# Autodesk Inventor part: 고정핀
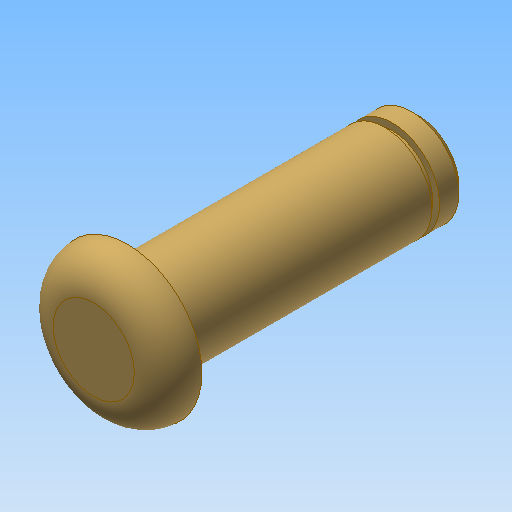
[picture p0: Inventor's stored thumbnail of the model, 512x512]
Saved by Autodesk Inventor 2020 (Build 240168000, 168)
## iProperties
Created: 2010-03
Part Number: 고정핀
Document SubType Name: Modeling
Designer: Administrator
Density: 1 g/cm^3
Material: 강철, 연강
Appearance: 기본값(1)
Author: Administrator
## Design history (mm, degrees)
sketch "스케치1"
  geometry: L1 (16.577, 14.126)-(28.417, -20.867) reference; L2 (-28.417, -20.867)-(-16.577, 14.126) reference; C1 r 18.5 at (0, -30.483) reference; C2 r 7 at (0, 8.517) reference; A1 r 17.5 centre (0, 8.517) between (16.577, 14.126) and (-16.577, 14.126) reference; A2 r 30 centre (0, -30.483) between (-28.417, -20.867) and (28.417, -20.867) reference
extrude "돌출1" new body sketch "스케치1" distance "d0" = 43; taper "d1" = 0 deg
sketch "스케치2"
  geometry: C1 r 7 at (0, 0) reference; C2 r 11 at (0, 0); 1 further point
  constraints: 1 centre point, 1 coincident
  dimensions: "d2" = 22 diameter of C2
extrude "돌출2" join sketch "스케치2" distance "d3" = 5; taper "d4" = 0 deg
fillet "모깎기1" dims "d5" = 5
sketch "스케치4"
  geometry: L1 (-20.867, -38)-(14.126, -38) reference; L2 (15.517, -43)-(1.517, -43) reference; L3 (8.517, -43)-(8.517, -38); L4 (1.517, 0)-(1.517, -43) reference; L5 (1.517, -38)-(2.517, -38); L6 (2.517, -38)-(2.517, -39.15); L7 (2.517, -39.15)-(1.517, -39.15); L8 (1.517, -39.15)-(1.517, -38); 1 further point
  constraints: 12 end point, 3 point on line, 2 horizontal, 2 parallel, 2 perpendicular, 1 midpoint, 2 other
  dimensions: "d10" = 12 diameter of L6 L3; "d13" = 1.15 distance between parallel lines of L7 L1
revolve "회전1" sketch "스케치4" stored, may be unused: angle "d14" = 90 deg
chamfer "모따기1" distance "d15" = 1; stored, may be unused: second distance "d16" = 2, angle "d17" = 45 deg
node "솔리드1"
node "참조1"
